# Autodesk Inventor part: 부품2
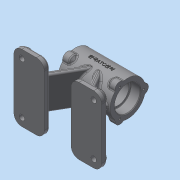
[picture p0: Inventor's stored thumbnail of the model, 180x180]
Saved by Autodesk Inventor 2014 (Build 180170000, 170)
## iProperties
Created: 2026-04
Part Number: 부품2
Material: 일반
Document SubType Name: Modeling
Designer: dg
Density: 1 g/cm^3
Appearance: 기본값
Author: dg
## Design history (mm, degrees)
sketch "스케치1"
  geometry: L1 (0, 0)-(-43, 0); L2 (0, 0)-(43, 0); L3 (-43, 0)-(-43, 29); L4 (43, 0)-(43, 29); L5 (-43, 0)-(43, 0); L6 (-43, 29)-(43, 29)
  constraints: 12 end point, 2 collinear, 1 horizontal, 1 perpendicular
  dimensions: "d20" = 43 distance from line of L3 L1.start; "d21" = 43 distance from line of L4 L1.start; "d22" = 58 diameter of L6 L1
revolve "회전3" stored, may be unused: angle "d23" = 90 deg
sketch "스케치4"
  geometry: L1 (0, 0)-(0, 37.954); L2 (0, 23.727)-(-6, 23.727); L3 (-6, 23.727)-(-6, 32); L4 (-6, 32)-(0, 32); L5 (0, 32)-(0, 23.727); L6 (-43, 29)-(43, 29) reference
  constraints: 10 end point, 2 parallel, 1 horizontal, 1 perpendicular, 1 point on line, 1 vertical
  dimensions: "d38" = 3 distance between parallel lines of L6 L4; "d39" = 12 diameter of L3 L1
revolve "회전5" sketch "스케치4" stored, may be unused: angle "d40" = 90 deg
sketch "스케치5" dims "d41" = 52
  geometry: L1 (0, 0)-(0, 40.395); C1 r 22 at (0, 0) reference; C2 r 8 at (0, 26)
  constraints: 2 end point, 1 centre point, 1 coincident, 1 point on line, 1 vertical, 1 vertical alignment, 2 other
  dimensions: "d42" = 16 diameter of C2
extrude "돌출1" join sketch "스케치5" distance "d43" = 10; taper "d44" = 0 deg
fillet "모깎기3" dims "d65" = 3
sketch "스케치8"
  geometry: A1 r 6 centre (0, 0) between (6, 0) and (-6, 0) reference; 1 further point
  constraints: 1 coincident
hole "구멍2" sketch "스케치8" at (0, 0) diameter "d73" = 5.188; stored, may be unused: countersink angle "d77" = 90 deg, drill point angle "d79" = 118 deg; dims "d74" = 18, "d75" = 7, "d76" = 2, "d78" = 20
sketch "스케치9"
  geometry: C1 r 8 at (0, 26); C2 r 21 at (0, 0) reference; A1 r 8 centre (0, 26) between (7.761, 27.942) and (-7.761, 27.942) reference
  constraints: 1 centre point, 1 coincident
extrude "돌출2" join sketch "스케치9" distance "d80" = 10; taper "d81" = -45 deg
sketch "스케치10"
  geometry: L1 (0, 0)-(-43, 0); L2 (0, 0)-(43, 0); L3 (27, 0)-(-27, 0); L4 (-27, 0)-(-27, 18); L5 (-27, 18)-(27, 18); L6 (27, 18)-(27, 0); L7 (-27, 0)-(-43, 0); L8 (-43, 0)-(-43, 21); L9 (-43, 21)-(-27, 21); L10 (-27, 21)-(-27, 0); L11 (27, 0)-(43, 0); L12 (43, 0)-(43, 21); L13 (43, 21)-(27, 21); L14 (27, 21)-(27, 0); L15 (-43, -7.25)-(-43, 27.942) reference; L16 (43, -7.25)-(43, 27.942) reference
  constraints: 28 end point, 7 equal length, 4 horizontal, 3 perpendicular, 1 point on line
  dimensions: "d85" = 43 distance of L1.start L1.end; "d86" = 43 distance of L1.start L2.end; "d87" = 0 distance between parallel lines of L15 L8; "d88" = 0 distance between parallel lines of L16 L12; "d89" = 16 distance between parallel lines of L16 L14; "d90" = 16 distance between parallel lines of L15 L4; "d91" = 36 diameter of L5 L1; "d92" = 42 diameter of L9 L1; "d93" = 42 diameter of L13 L2
revolve "회전7" stored, may be unused: angle "d97" = 90 deg
fillet "모깎기4" dims "d98" = 0.6
chamfer "모따기3" distance "d99" = 1; stored, may be unused: second distance "d100" = 2, angle "d101" = 45 deg
sketch "스케치11"
  geometry: A1 r 8 centre (22.517, -39) between (20.318, -46.692) and (28.079, -33.25) reference; A2 r 8 centre (0, 0) between (7.761, 1.942) and (-7.761, 1.942) reference; A3 r 8 centre (-22.517, -39) between (-28.079, -33.25) and (-20.318, -46.692) reference; 3 further points
  constraints: 3 coincident
hole "구멍3" sketch "스케치11" at (0, 0), (22.517, -39), (-22.517, -39) diameter "d102" = 3.242; stored, may be unused: countersink angle "d106" = 90 deg, drill point angle "d108" = 118 deg; dims "d103" = 8, "d104" = 7, "d105" = 2, "d107" = 10
fillet "모깎기5" dims "d109" = 3
fillet "모깎기6" dims "d110" = 3
node "작업 평면1"
sketch "스케치12"
  geometry: L1 (72, -55)-(22, -55); L2 (22, -55)-(22, 55); L3 (22, 55)-(72, 55); L4 (72, 55)-(72, -55); L5 (-22, -55)-(-72, -55); L6 (-72, -55)-(-72, 55); L7 (-72, 55)-(-22, 55); L8 (-22, 55)-(-22, -55); 1 further point
  constraints: 16 end point, 4 parallel, 2 horizontal, 2 perpendicular
  dimensions: "d112" = 22 distance from line of L2 point (0, 0); "d113" = 22 distance from line of L8 point (0, 0); "d114" = 55 distance from line of L1 point (0, 0); "d115" = 55 distance from line of L3 point (0, 0); "d116" = 55 distance from line of L5 point (0, 0); "d117" = 55 distance from line of L7 point (0, 0); "d118" = 72 distance from line of L4 point (0, 0); "d119" = 72 distance from line of L6 point (0, 0)
extrude "돌출3" join sketch "스케치12" distance "d120" = 9; taper "d121" = 0 deg
sketch "스케치13"
  geometry: L1 (-22, -63)-(-72, -63) reference; L2 (-32, -63)-(5.437, 1.842); L3 (0, 0)-(0, -63.918); L4 (-41.238, -63)-(-3.801, 1.842); L5 (-41.238, -63)-(-32, -63); L6 (5.437, 1.842)-(-3.801, 1.842)
  constraints: 10 end point, 2 parallel, 2 point on line, 1 collinear, 1 perpendicular
  dimensions: "d122" = 30 deg angle of L3 L2; "d123" = 10 distance of L2.start L1.start; "d124" = 8 distance between parallel lines of L2 L4
extrude "돌출4" join sketch "스케치13" stored distance "d125" = 54; taper "d126" = 0 deg
sketch "스케치14"
  geometry: L1 (-41.238, -63)-(-10.975, -10.583) reference; L2 (-22, -63)-(-72, -63) reference; L3 (-41.238, -63)-(-12.569, -13.345); L4 (-55.094, -63)-(-26.425, -13.345); L5 (-55.094, -63)-(-41.238, -63); L6 (-12.569, -13.345)-(-26.425, -13.345); 1 further point
  constraints: 8 end point, 2 parallel, 2 point on line, 1 collinear
  dimensions: "d127" = 12 distance between parallel lines of L1 L4
extrude "돌출5" join sketch "스케치14" stored distance "d128" = 10; taper "d129" = 0 deg
sketch "스케치15"
  geometry: L1 (0, 0)-(-43, 0); L2 (0, 0)-(43, 0); L3 (27, 0)-(-27, 0); L4 (-27, 0)-(-27, 18); L5 (-27, 18)-(27, 18); L6 (27, 18)-(27, 0); L7 (-27, 0)-(-43, 0); L8 (-43, 0)-(-43, 21); L9 (-43, 21)-(-27, 21); L10 (-27, 21)-(-27, 0); L11 (27, 0)-(43, 0); L12 (43, 0)-(43, 21); L13 (43, 21)-(27, 21); L14 (27, 21)-(27, 0); L15 (-43, 22)-(-43, -22) reference; L16 (43, -22)-(43, 22) reference
  constraints: 28 end point, 7 equal length, 4 horizontal, 3 perpendicular, 1 point on line
  dimensions: "d130" = 43 distance of L1.start L1.end; "d131" = 43 distance of L1.start L2.end; "d132" = 0 distance between parallel lines of L16 L12; "d133" = 0 distance between parallel lines of L15 L8; "d134" = 16 distance between parallel lines of L15 L4; "d135" = 16 distance between parallel lines of L16 L14; "d136" = 42 diameter of L9 L1; "d137" = 42 diameter of L13 L2; "d138" = 36 diameter of L5 L2
revolve "회전8" sketch "스케치15" stored, may be unused: angle "d139" = 90 deg
fillet "모깎기7" dims "d140" = 0.6
fillet "모깎기8" dims "d141" = 13
fillet "모깎기9" dims "d142" = 3
fillet "모깎기10" dims "d143" = 3
fillet "모깎기11" dims "d144" = 3
fillet "모깎기12" dims "d145" = 3
sketch "스케치16"
  geometry: C1 r 9 at (59, 42); A1 r 10 centre (59, 42) between (69, 42) and (59, 52) reference; 1 further point
  constraints: 1 centre point, 1 coincident
  dimensions: "d146" = 18 diameter of C1
extrude "돌출6" join sketch "스케치16" distance "d147" = 3; taper "d148" = 0 deg
sketch "스케치17"
  geometry: C1 r 9 at (0, 0) reference; 2 further points
  constraints: 1 coincident
hole "구멍4" sketch "스케치17" at (0, 0) diameter "d149" = 9; stored, may be unused: countersink angle "d153" = 90 deg, drill point angle "d155" = 118 deg; dims "d150" = 8, "d151" = 7, "d152" = 2, "d154" = 10
fillet "모깎기13" dims "d156" = 3
node "작업 평면2"
sketch "스케치18"
  geometry: L1 (35, -72)-(22, -72) reference; 2 further points
  constraints: 1 coincident, 1 other
  dimensions: "d157" = 72 distance from line of L1 point (0, 0)
feature "엠보싱1" sketch "스케치18" dims "d158" = 0.5, "d159" = 0
node "솔리드1"
mirror "대칭1"
mirror "대칭2"
pattern_circular "원형 패턴2" dims angle "d49" = 360 deg
mirror "대칭3"
mirror "대칭5"
mirror "대칭6"
pattern_circular "원형 패턴4" dims angle "d95" = 360 deg
mirror "대칭7"
mirror "대칭8"
mirror "대칭9"
mirror "대칭10"
mirror "대칭11"
mirror "대칭12"
mirror "대칭13"
other parameters: "d111" = -72
